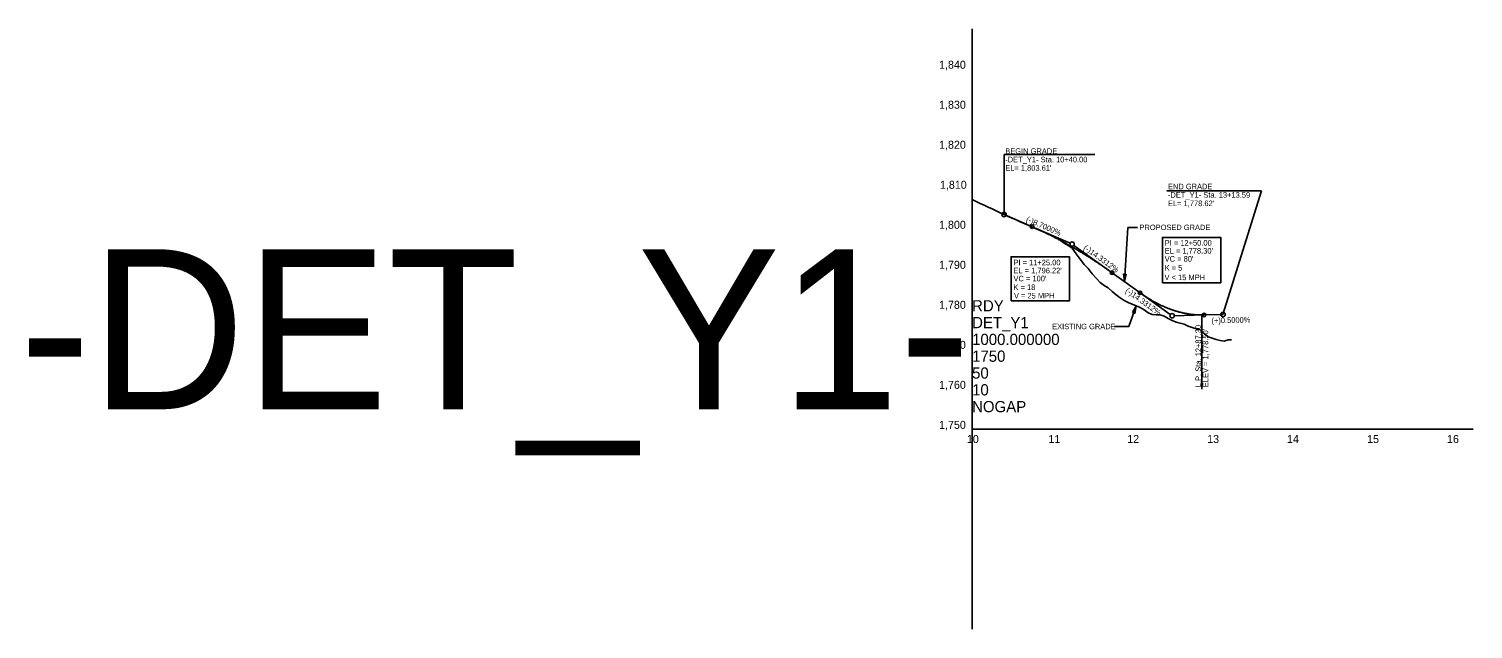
# Model space of a CAD drawing. Extents: x 498575 to 532350, y 405181 to 484585.
# Drawn here: x 504691 to 506496, y 478740 to 479490 of the extents above; entities that cross this region are included whole.
import ezdxf

# ---------------------------------------------------------------- set-up
doc = ezdxf.new("R2010")
doc.units = 0
for name, color, linetype in [('Exist Profile Cell', 7, 'Continuous'), ('Exist Vertical Profile Ground Line', 7, 'Continuous'), ('Exist Vertical Profile Horizontal Axis Label Major', 7, 'Continuous'), ('Exist Vertical Profile Vertical Axis Label', 7, 'Continuous'), ('Prop Grid Mask', 7, 'Continuous'), ('Prop PFL Text', 7, 'Continuous'), ('Prop Vertical Profile Curve Label', 7, 'Continuous'), ('Prop Vertical Profile Grade', 7, 'Continuous'), ('Prop Vertical Profile Grade Label', 7, 'Continuous'), ('Prop Vertical Profile Strip Grade', 7, 'Continuous'), ('Prop VPI Label', 7, 'Continuous'), ('Scratch_Level_7', 7, 'Continuous'), ('Typical Terminator CELL', 7, 'Continuous')]:
    doc.layers.add(name, color=color, linetype=linetype)

# ---------------------------------------------------------------- blocks, each defined once
blk = doc.blocks.new('TERMINATOR')
at = {"layer": 'Typical Terminator CELL'}
blk.add_lwpolyline([(-0.469, 0.081), (0, 0), (-0.471, -0.083), (-0.411, 0)], close=True, dxfattribs=at)

msp = doc.modelspace()

# ---------------------------------------------------------------- linework, layer by layer
at = {"layer": 'Exist Profile Cell'}
for q in [(505869.8, 479489.7), (506496, 478989.7), (505869.8, 478739.7)]:
    msp.add_line((505869.8, 478989.7), q, dxfattribs=at)
at = {"layer": 'Exist Vertical Profile Ground Line'}
msp.add_lwpolyline([(505869.8, 479276.5), (505874.8, 479274.1), (505879.8, 479271.7), (505884.8, 479269.3), (505889.8, 479267), (505894.8, 479264.7), (505899.8, 479262.3), (505904.8, 479260), (505909.8, 479257.7), (505914.8, 479255.4), (505919.8, 479253.2), (505924.8, 479250.9), (505929.8, 479248.7), (505934.8, 479246.5), (505939.8, 479244.4), (505944.8, 479242.2), (505949.8, 479240), (505954.8, 479237.7), (505959.8, 479235.5), (505964.8, 479233.3), (505969.8, 479231), (505974.8, 479228.5), (505979.8, 479225.7), (505984.8, 479222), (505989.8, 479218.9), (505994.8, 479215.8), (505999.8, 479208.8), (506004.8, 479201.8), (506009.8, 479195.2), (506014.8, 479190.2), (506019.8, 479183.7), (506024.8, 479178), (506029.8, 479172.6), (506034.8, 479168.9), (506039.8, 479166.1), (506044.8, 479161.5), (506049.8, 479157.5), (506054.8, 479153.7), (506059.8, 479150.3), (506064.8, 479147.9), (506069.8, 479145.7), (506074.8, 479143.5), (506079.8, 479141.5), (506084.8, 479138.8), (506089.8, 479134.7), (506094.8, 479132.8), (506099.8, 479132.2), (506104.8, 479132.4), (506109.8, 479130.9), (506114.8, 479127.7), (506119.8, 479125.1), (506124.8, 479123.3), (506129.8, 479121.9), (506134.8, 479120.7), (506139.8, 479118.4), (506144.8, 479116.5), (506149.8, 479115), (506154.8, 479113.8), (506159.8, 479109), (506164.8, 479105), (506169.8, 479103.2), (506174.8, 479101.7), (506179.8, 479100.5), (506184.8, 479099.6), (506189.8, 479101), (506194.1, 479101)], dxfattribs=at)
at = {"layer": 'Prop Grid Mask'}
for points in [[(506107.6, 479172.5), (506180.6, 479172.5), (506180.6, 479229.2), (506107.6, 479229.2)], [(505918.5, 479149.7), (505991.5, 479149.7), (505991.5, 479205), (505918.5, 479205)]]:
    msp.add_lwpolyline(points, close=True, dxfattribs=at)
at = {"layer": 'Prop PFL Text'}
for p, q in [((506064.5, 479241.3), (506060.1, 479173.9)), ((506076.4, 479241.3), (506064.5, 479241.3)), ((506065.5, 479117.8), (506074.8, 479143.7)), ((506065.5, 479117.8), (506047.6, 479117.8))]:
    msp.add_line(p, q, dxfattribs=at)
at = {"layer": 'Prop Vertical Profile Curve Label'}
for centre in [(505944.8, 479242.5), (506044.8, 479184.9), (506079.8, 479159.9), (506159.8, 479132.2)]:
    msp.add_circle(centre, 2.25, dxfattribs=at)
at = {"layer": 'Prop Vertical Profile Grade'}
for p, q in [((505909.8, 479257.7), (505944.8, 479242.5)), ((506044.8, 479184.9), (506079.8, 479159.9)), ((506159.8, 479132.2), (506183.4, 479132.8))]:
    msp.add_line(p, q, dxfattribs=at)
for points in [[(505944.8, 479242.5), (505946.8, 479241.6), (505948.8, 479240.8), (505950.8, 479239.9), (505952.8, 479238.9), (505954.8, 479238), (505956.8, 479237.1), (505958.8, 479236.1), (505960.8, 479235.2), (505962.8, 479234.2), (505964.8, 479233.3), (505966.8, 479232.3), (505968.8, 479231.3), (505970.8, 479230.3), (505972.8, 479229.2), (505974.8, 479228.2), (505976.8, 479227.2), (505978.8, 479226.1), (505980.8, 479225), (505982.8, 479224), (505984.8, 479222.9), (505986.8, 479221.8), (505988.8, 479220.6), (505990.8, 479219.5), (505992.8, 479218.4), (505994.8, 479217.2), (505996.8, 479216.1), (505998.8, 479214.9), (506000.8, 479213.7), (506002.8, 479212.5), (506004.8, 479211.3), (506006.8, 479210.1), (506008.8, 479208.9), (506010.8, 479207.7), (506012.8, 479206.4), (506014.8, 479205.2), (506016.8, 479203.9), (506018.8, 479202.6), (506020.8, 479201.3), (506022.8, 479200), (506024.8, 479198.7), (506026.8, 479197.4), (506028.8, 479196), (506030.8, 479194.7), (506032.8, 479193.3), (506034.8, 479192), (506036.8, 479190.6), (506038.8, 479189.2), (506040.8, 479187.8), (506042.8, 479186.4), (506044.8, 479184.9)], [(506079.8, 479159.9), (506081.4, 479158.7), (506083, 479157.6), (506084.6, 479156.5), (506086.2, 479155.5), (506087.8, 479154.4), (506089.4, 479153.4), (506091, 479152.4), (506092.6, 479151.4), (506094.2, 479150.5), (506095.8, 479149.6), (506097.4, 479148.7), (506099, 479147.8), (506100.6, 479147), (506102.2, 479146.1), (506103.8, 479145.3), (506105.4, 479144.5), (506107, 479143.8), (506108.6, 479143.1), (506110.2, 479142.4), (506111.8, 479141.7), (506113.4, 479141), (506115, 479140.4), (506116.6, 479139.8), (506118.2, 479139.2), (506119.8, 479138.6), (506121.4, 479138.1), (506123, 479137.5), (506124.6, 479137.1), (506126.2, 479136.6), (506127.8, 479136.1), (506129.4, 479135.7), (506131, 479135.3), (506132.6, 479134.9), (506134.2, 479134.6), (506135.8, 479134.3), (506137.4, 479134), (506139, 479133.7), (506140.6, 479133.4), (506142.2, 479133.2), (506143.8, 479133), (506145.4, 479132.8), (506147, 479132.6), (506148.6, 479132.5), (506150.2, 479132.4), (506151.8, 479132.3), (506153.4, 479132.2), (506155, 479132.2), (506156.6, 479132.2), (506158.2, 479132.2), (506159.8, 479132.2)]]:
    msp.add_spline(points, degree=3, dxfattribs=at)
at = {"layer": 'Prop Vertical Profile Strip Grade'}
msp.add_line((506157.1, 479131.7), (506157.1, 479039.5), dxfattribs=at)
at = {"layer": 'Prop VPI Label'}
for p, q in [((505909.8, 479257.7), (505909.8, 479332.8)), ((506023, 479332.8), (505909.8, 479332.8)), ((506231.7, 479287.3), (506113.1, 479287.3)), ((506183.4, 479132.8), (506231.7, 479287.3)), ((505944.8, 479242.5), (505992.2, 479221.9)), ((506044.8, 479184.9), (505997, 479219.2)), ((506079.8, 479159.9), (506117.5, 479132.8)), ((506159.8, 479132.2), (506122.5, 479131.3))]:
    msp.add_line(p, q, dxfattribs=at)
for centre in [(505909.8, 479257.7), (505994.8, 479220.8), (506119.8, 479131.2), (506183.4, 479132.8)]:
    msp.add_circle(centre, 2.75, dxfattribs=at)

# ---------------------------------------------------------------- block references
at = {"layer": 'Prop PFL Text', "xscale": 20}
for p, yscale, rotation in [((506060.1, 479173.9), 19.999999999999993, -93.70508386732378), ((506074.8, 479143.5), 20, 70.13551694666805)]:
    msp.add_blockref('TERMINATOR', p, dxfattribs=dict(at, yscale=yscale, rotation=rotation))

# ---------------------------------------------------------------- texts
at = {"layer": 'Exist Profile Cell'}
for s, p in [('RDY', (505869.8, 479136.7)), ('DET_Y1', (505869.8, 479115.7)), ('1000.000000', (505869.8, 479094.7)), ('1750', (505869.8, 479073.7)), ('50', (505869.8, 479052.7)), ('10', (505869.8, 479031.7)), ('NOGAP', (505869.8, 479010.7))]:
    msp.add_text(s, height=14, dxfattribs=at).set_placement(p)
at = {"layer": 'Exist Vertical Profile Horizontal Axis Label Major'}
for s, p in [('10', (505863.3, 478972.2)), ('11', (505965.2, 478972.2)), ('12', (506063.7, 478972.2)), ('13', (506163.6, 478972.2)), ('14', (506263.4, 478972.2)), ('15', (506363.5, 478972.2)), ('16', (506463.4, 478972.2))]:
    msp.add_text(s, height=10, dxfattribs=at).set_placement(p)
at = {"layer": 'Exist Vertical Profile Vertical Axis Label'}
for s, p in [('1,840', (505828.5, 479439.9)), ('1,830', (505828.5, 479389.9)), ('1,820', (505828.5, 479339.9)), ('1,810', (505829.6, 479289.9)), ('1,800', (505828.5, 479239.9)), ('1,790', (505828.5, 479189.9)), ('1,780', (505828.5, 479139.9)), ('1,770', (505828.5, 479089.9)), ('1,760', (505828.5, 479039.9)), ('1,750', (505828.5, 478989.9))]:
    msp.add_text(s, height=10, dxfattribs=at).set_placement(p)
at = {"layer": 'Prop PFL Text'}
for s, p in [('PROPOSED GRADE', (506079, 479238.3)), ('EXISTING GRADE', (505969.9, 479114.4))]:
    msp.add_text(s, height=6.75, dxfattribs=at).set_placement(p)
at = {"layer": 'Prop Vertical Profile Curve Label'}
for s, p in [("VC = 80'", (506110.5, 479198.8)), ("VC = 100'", (505921.5, 479174.2)), ('K = 5', (506110.5, 479187.6)), ('K = 18', (505921.5, 479163.3)), ('V = 25 MPH', (505922.1, 479152.8))]:
    msp.add_text(s, height=7, dxfattribs=at).set_placement(p)
at = {"layer": 'Prop Vertical Profile Grade Label'}
for s, rotation, p in [('(-)8.7000%', 336.491, (505936.6, 479249.3)), ('(-)14.3312%', 324.3761, (506008.3, 479214.7)), ('(-)14.3312%', 324.3761, (506060.7, 479161.2)), ('(+)0.5000%', 1.432, (506169.1, 479121.6))]:
    msp.add_text(s, height=7, rotation=rotation, dxfattribs=at).set_placement(p)
at = {"layer": 'Prop Vertical Profile Strip Grade'}
for s, p in [('L.P. Sta. 12+87.30', (506156, 479042)), ("ELEV = 1,778.50'", (506164.9, 479042))]:
    msp.add_text(s, height=7, rotation=90, dxfattribs=at).set_placement(p)
at = {"layer": 'Prop VPI Label'}
for s, p in [('-DET_Y1- Sta. 10+40.00', (505911.2, 479322.9)), ('BEGIN GRADE', (505911.2, 479333.4)), ("EL= 1,803.61'", (505911.2, 479312.4)), ('END GRADE', (506114.6, 479289.2)), ('-DET_Y1- Sta. 13+13.59', (506114.6, 479278.7)), ("EL= 1,778.62'", (506114.6, 479268.2)), ('PI = 12+50.00', (506110.5, 479218.8)), ("EL = 1,778.30'", (506110.5, 479208.8)), ('PI = 11+25.00', (505921.5, 479194.2)), ("EL = 1,796.22'", (505921.5, 479184.2)), ('V < 15 MPH', (506110.3, 479175.7))]:
    msp.add_text(s, height=7, dxfattribs=at).set_placement(p)
at = {"layer": 'Scratch_Level_7'}
msp.add_text('-DET_Y1-', height=200, dxfattribs=at).set_placement((504678.9, 479014.4))

doc.saveas('drawing.dxf')
